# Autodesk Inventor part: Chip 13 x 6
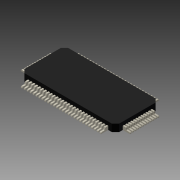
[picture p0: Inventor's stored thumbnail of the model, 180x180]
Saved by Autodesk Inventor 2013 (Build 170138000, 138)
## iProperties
Company: Autodesk Inc.
Created: 2005-12
Part Number: Chip 13 x 6
Document SubType Name: Modeling
Designer: Autodesk Inc.
Density: 1 g/cm^3
Mass: 0.0827827 g
Surface Area: 2.7367 cm^2
Volume: 0.0827827 cm^3
Material: Allgemein
Title: Personal Computer
Author: Autodesk Inc.
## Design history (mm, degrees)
sketch "Sketch1"
  geometry: L1 (0, 4.2)-(0, -4.2) reference; L2 (-9.1, 0)-(9.1, 0) reference; L3 (-6.5, 3)-(6.5, 3); L4 (6.5, 3)-(6.5, -3); L5 (6.5, -3)-(-6.5, -3); L6 (-6.5, -3)-(-6.5, 3)
  constraints: 8 end point, 2 parallel, 1 horizontal, 1 perpendicular, 2 other
  dimensions: "d0" = 13 distance of L3.start L3.end; "d1" = 6 distance of L5.end L3.start
extrude "Extrusion1" new body sketch "Sketch1" distance "d2" = 1; taper "d3" = 0 deg
workplane "Work Plane1"
sketch "Sketch3"
  geometry: L1 (13, 0)-(13, 1) reference; L2 (13, 0)-(0, 0) reference; L3 (13, 0)-(14.221, 0); L4 (13, 0.5)-(13.328, 0.5); L5 (13.423, 0.432)-(13.477, 0.268); L6 (13.572, 0.2)-(13.85, 0.2); L7 (14, 0.05)-(14, 0); L8 (13, 0)-(14, 0); L9 (13, 0)-(13, 0.5); A1 r 0.1 centre (13.328, 0.4) between (13.423, 0.432) and (13.328, 0.5); A2 r 0.1 centre (13.572, 0.3) between (13.477, 0.268) and (13.572, 0.2); A3 r 0.15 centre (13.85, 0.05) between (14, 0.05) and (13.85, 0.2); 3 further points
  constraints: 14 end point, 7 point on line, 6 point on circle, 6 tangent, 3 centre point, 3 collinear, 2 parallel, 1 equal radius, 1 midpoint, 1 perpendicular
  dimensions: "d13" = 1 distance between parallel lines of L9 L7; "d14" = 0.4 distance of L4.start point (13.4, 0.5); "d15" = 0.2 distance of point (14, 0.2) L7.end; "d16" = 0.5 distance of point (13.5, 0.2) point (14, 0.2); "d17" = 0.1 radius of A1; "d18" = 0.15 radius of A3
extrude "Extrusion3" join sketch "Sketch3" distance "d19" = 0.2; taper "d20" = 0 deg
pattern_linear "Rectangular Pattern2" dims "d23" = 3.8
mirror "Mirror3"
workplane "Work Plane3"
sketch "Sketch5"
  geometry: L1 (1, 0)-(0, 0) reference; L2 (1, 1)-(1, 0) reference; L3 (1, 0)-(1, -1.562); L4 (0.5, 0)-(0.5, -0.328); L5 (0.568, -0.423)-(0.732, -0.477); L6 (0.8, -0.572)-(0.8, -0.85); L7 (0.95, -1)-(1, -1); L8 (1, 0)-(1, -1); L9 (0.5, 0)-(1, 0); A1 r 0.15 centre (0.95, -0.85) between (0.8, -0.85) and (0.95, -1); A2 r 0.1 centre (0.6, -0.328) between (0.5, -0.328) and (0.568, -0.423); A3 r 0.1 centre (0.7, -0.572) between (0.8, -0.572) and (0.732, -0.477); 3 further points
  constraints: 14 end point, 7 point on line, 6 point on circle, 6 tangent, 3 centre point, 3 collinear, 2 parallel, 1 equal radius, 1 midpoint, 1 perpendicular
  dimensions: "d25" = 0.2 distance of point (0.8, -1) L7.end; "d26" = 0.5 distance of point (0.8, -0.5) point (0.8, -1); "d27" = 0.4 distance of L4.start point (0.5, -0.4); "d28" = 1 distance between parallel lines of L1 L7; "d29" = 0.15 radius of A1; "d30" = 0.1 radius of A2
extrude "Extrusion4" join sketch "Sketch5" distance "d31" = 0.2; taper "d32" = 0 deg
mirror "Mirror4"
chamfer "Chamfer1" distance "d36" = 0.5; stored, may be unused: second distance "d37" = 2, angle "d38" = 45 deg
body "Solid1"
pattern_linear "Rectangular Pattern3" dims "d35" = 10.8
other parameters: "d4" = -1, "d24" = -1
